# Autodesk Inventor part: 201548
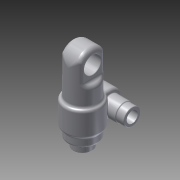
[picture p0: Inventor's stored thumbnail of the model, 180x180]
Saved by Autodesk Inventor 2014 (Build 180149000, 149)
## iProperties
Created: 2007-10
Part Number: 201548
Document SubType Name: Modeling
Designer: TH
Density: 1.06 g/cm^3
Mass: 17.0659 g
Surface Area: 97.1751 cm^2
Volume: 16.0999 cm^3
Material: ABS Plastic
Description: WORM GEAR HOUSING
Appearance: Smooth - White
Component Category: Lower Component
Author: TH
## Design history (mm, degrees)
workplane "Work Plane1"
sketch "Sketch2"
  geometry: C1 r 10.5 at (0, 0); 1 further point
  constraints: 1 centre point, 1 coincident
  dimensions: "d2" = 21 diameter of C1
extrude "Extrusion1" new body sketch "Sketch2" distance "d3" = 58.28; taper "d4" = 0 deg
sketch "Sketch3"
  geometry: C1 r 6 at (0, 0); 1 further point
  constraints: 1 centre point, 1 coincident
  dimensions: "d5" = 12 diameter of C1
extrude "Extrusion2" cut sketch "Sketch3" stored distance "d6" = 58.28; taper "d7" = 0 deg
sketch "Sketch4"
  geometry: L1 (-7.217, 7.627)-(-7.217, -7.627); L2 (7.217, 7.627)-(7.217, -7.627); A1 r 10.5 centre (0, 0) between (-7.217, 7.627) and (-7.217, -7.627) reference
  constraints: 4 end point, 4 point on circle, 1 parallel, 1 vertical
  dimensions: "d8" = 7.217 distance from line of L1 A1.centre; "d9" = 7.217 distance from line of L2 A1.centre (= d8)
extrude "Extrusion3" cut sketch "Sketch4" distance "d10" = 20.38; taper "d11" = 0 deg
sketch "Sketch5"
  geometry: L1 (10.5, 10.229)-(10.5, -48.051) reference; L2 (-10.5, 10.229)-(-10.5, -48.051) reference; L3 (0, 0)-(0, 10.229); L4 (0, 10.229)-(10.5, 10.229); L5 (10.5, 10.229)-(10.5, -0.271); L6 (-10.5, -0.271)-(-10.5, 10.229); L7 (-10.5, 10.229)-(0, 10.229); A1 r 10.5 centre (0, -0.271) between (0, 10.229) and (10.5, -0.271)
  constraints: 10 end point, 3 point on circle, 3 point on line, 3 tangent, 1 centre point, 1 collinear, 1 parallel
extrude "Extrusion4" cut sketch "Sketch5" stored distance "d13" = 20.38; taper "d14" = 0 deg
fillet "Fillet1" dims "d15" = 2.44
fillet "Fillet2" dims "d16" = 2.17
fillet "Fillet3" dims "d17" = 3
fillet "Fillet4" dims "d18" = 0.5
workplane "Work Plane2"
sketch "Sketch6"
  geometry: L1 (0, 0)-(0, 15.87); L2 (-6, 10.966)-(6, 10.966); L3 (6, 10.966)-(6, 22.966); L4 (6, 22.966)-(-6, 22.966); L5 (-6, 22.966)-(-6, 10.966); A1 r 12.5 centre (0, 0) between (-6, 10.966) and (6, 10.966); 1 further point
  constraints: 10 end point, 2 parallel, 2 point on circle, 1 centre point, 1 coincident, 1 horizontal, 1 perpendicular, 1 vertical
  dimensions: "d20" = 15.87 distance of L1.start L1.end; "d21" = 25 diameter of A1; "d22" = 12 distance of L3.end L4.end; "d24" = 12 distance between parallel lines of L2 L4 (= d22)
extrude "Extrusion5" join sketch "Sketch6" distance "d25" = 18.02; taper "d26" = 0 deg
fillet "Fillet5" dims "d27" = 9.01
fillet "Fillet6" dims "d28" = 2
fillet "Fillet7" dims "d29" = 2
sketch "Sketch7"
  geometry: C1 r 6.5 at (13.956, -32.01); A1 r 9.01 centre (13.956, -32.01) between (13.956, -41.02) and (13.956, -23) reference; A2 r 9.01 centre (13.956, -32.01) between (13.956, -41.02) and (13.956, -23) reference; 1 further point
  constraints: 1 centre point, 1 coincident
  dimensions: "d30" = 13 diameter of C1
extrude "Extrusion6" join sketch "Sketch7" stored distance "d31" = 32; taper "d32" = 0 deg
sketch "Sketch8"
  geometry: C1 r 6 at (13.956, -32.01); A1 r 9.01 centre (13.956, -32.01) between (13.956, -41.02) and (13.956, -23) reference; A2 r 9.01 centre (13.956, -32.01) between (13.956, -41.02) and (13.956, -23) reference; 1 further point
  constraints: 1 centre point, 1 coincident
  dimensions: "d33" = 12 diameter of C1
extrude "Extrusion7" join sketch "Sketch8" stored distance "d34" = 43; taper "d35" = 0 deg
fillet "Fillet8" dims "d36" = 0.5
sketch "Sketch9"
  geometry: C1 r 4 at (13.956, -32.01); A1 r 9.01 centre (13.956, -32.01) between (13.956, -41.02) and (13.956, -23) reference; A2 r 9.01 centre (13.956, -32.01) between (13.956, -41.02) and (13.956, -23) reference; 1 further point
  constraints: 1 centre point, 1 coincident
  dimensions: "d37" = 8 diameter of C1
extrude "Extrusion8" cut sketch "Sketch9" stored distance "d38" = 43; taper "d39" = 0 deg
sketch "Sketch10"
  geometry: C1 r 10.5 at (0, 0) reference; C2 r 6.75 at (0, 0)
  constraints: 1 centre point, 1 coincident
  dimensions: "d40" = 13.5 diameter of C2
extrude "Extrusion9" join sketch "Sketch10" distance "d41" = 5.5; taper "d42" = 0 deg
fillet "Fillet9" dims "d43" = 2
fillet "Fillet10" dims "d44" = 0.5
sketch "Sketch11"
  geometry: L1 (6.25, -53.551)-(-6.25, -53.551) reference; L2 (0, -53.551)-(0, -46.051); L3 (0, -46.051)-(-6, -46.051); L4 (-6, -46.051)-(-6, -14.051); L5 (-6, -14.051)-(0, -14.051); L6 (0, -14.051)-(0, -46.051); L7 (-4.25, -46.051)-(-4.25, -53.551); L8 (-6, -25.76)-(-10.125, -25.76); L9 (-10.125, -25.76)-(-10.125, -38.26); L10 (-10.125, -38.26)-(-6, -38.26); L11 (-6, -38.26)-(-6, -25.76); L12 (13.956, -32.01)-(-10.125, -32.01); C1 r 4 at (13.956, -32.01) reference; C2 r 4 at (13.956, -32.01) reference; 1 further point
  constraints: 22 end point, 5 perpendicular, 4 parallel, 3 point on line, 2 midpoint, 1 collinear, 1 horizontal
  dimensions: "d45" = 8.5 diameter of L7 L6; "d46" = 12 diameter of L4 L6; "d47" = 7.5 distance between parallel lines of L3 L1; "d48" = 32 distance of L3.end L4.end; "d49" = 12.5 distance of L8.end L9.end; "d50" = 20.25 diameter of L9 L6
revolve "Revolution1" sketch "Sketch11" stored, may be unused: angle "d51" = 90 deg
sketch "Sketch12"
  geometry: L1 (-6, -38.26)-(6, -38.26) reference; L2 (-10.125, -38.26)-(10.125, -38.26) reference; L3 (-10.125, -25.76)-(10.125, -25.76) reference; L4 (-6, -25.76)-(6, -25.76) reference; L5 (10.125, -25.76)-(10.125, -38.26); L6 (6, -25.76)-(6, -38.26); L7 (6, -38.26)-(13.956, -38.26); L8 (6, -25.76)-(13.956, -25.76); C1 r 4 at (13.956, -32.01) reference; A1 r 6.25 centre (13.956, -32.01) between (13.956, -38.26) and (13.956, -25.76); 1 further point
  constraints: 8 end point, 2 point on circle, 2 point on line, 1 centre point, 1 coincident, 1 parallel, 1 perpendicular, 1 tangent
extrude "Extrusion10" cut sketch "Sketch12" stored distance "d52" = 10; taper "d53" = 0 deg
fillet "Fillet11" dims "d54" = 1
fillet "Fillet12" dims "d55" = 0.5
body "Solid1"
node "Projected Loop2"
node "Projected Loop3"
node "Projected Loop4"
node "Projected Loop5"
node "Projected Loop6"
node "Projected Loop7"
node "Projected Loop8"
other parameters: "d12" = 10.229, "d19" = -23
